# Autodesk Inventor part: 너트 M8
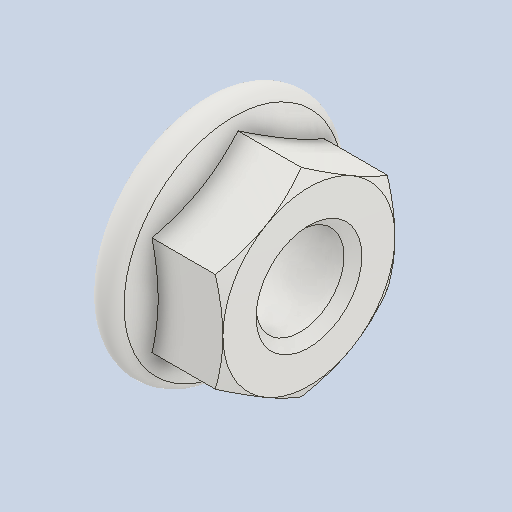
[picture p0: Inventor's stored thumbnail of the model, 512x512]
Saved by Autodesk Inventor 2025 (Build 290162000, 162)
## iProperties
Created: 2024-07
Part Number: 너트 M8
Material: 스테인리스강
Description: 플랜지붙이 6각 너트 - 일반 스레드
Document SubType Name: Modeling
Designer: parkm
Density: 8 g/cm^3
Appearance: 기본값
Author: jhkim
Sending System: Autodesk Inventor 2025
Preprocessor: ST-DEVELOPER v20
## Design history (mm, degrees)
feature "Solid1"
node "솔리드1"
